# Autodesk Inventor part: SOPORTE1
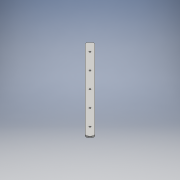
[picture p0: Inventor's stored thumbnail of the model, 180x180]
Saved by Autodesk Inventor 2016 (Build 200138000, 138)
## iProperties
Created: 2016-06
Part Number: SOPORTE1
Material: Genérico
Document SubType Name: Modeling
Designer: adm
Density: 1 g/cm^3
Appearance: Valor por defecto
Author: adm
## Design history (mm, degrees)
sketch "Boceto1"
  geometry: L1 (166.17, -187.383)-(187.383, -166.17); L2 (187.383, -166.17)-(-166.17, 187.383); L3 (-166.17, 187.383)-(-187.383, 166.17); L4 (-187.383, 166.17)-(166.17, -187.383); L5 (166.17, -187.383)-(-166.17, 187.383); L6 (187.383, -166.17)-(-187.383, 166.17); L7 (166.17, -187.383)-(196.17, -187.383); C1 r 3.5 at (-141.421, 141.421); C2 r 3.5 at (-70.711, 70.711); C3 r 3.5 at (0, 0); C4 r 3.5 at (70.711, -70.711); C5 r 3.5 at (141.421, -141.421); 6 further points
  constraints: 14 end point, 5 centre point, 5 coincident, 2 midpoint, 2 parallel, 1 equal length, 1 horizontal, 1 perpendicular
  dimensions: "d0" = 30 distance of L1.start L1.end; "d1" = 45 deg angle of L7 L1; "d2" = 500 distance of L2.end L1.end; "d3" = 50 distance from line of point (-141.421, 141.421) L3; "d4" = 50 distance from line of point (141.421, -141.421) L1; "d5" = 150 distance from line of point (-70.711, 70.711) L3; "d6" = 250 distance from line of point (0, 0) L3; "d7" = 350 distance from line of point (70.711, -70.711) L3; "d8" = 7 diameter of C1; "d9" = 7 diameter of C2; "d10" = 7 diameter of C3; "d11" = 7 diameter of C4; "d12" = 7 diameter of C5
extrude "Extrusión1" new body sketch "Boceto1" distance "d13" = 6; taper "d14" = 0 deg
fillet "Empalme1" dims "d15" = 10
sketch "Boceto2"
  geometry: L1 (75.83, -250.705)-(156.742, -154.277); L2 (57.177, -210.705)-(126.1, -128.566); L3 (34.196, -221.421)-(-203.95, -221.421); L4 (52.848, -261.421)-(-289.73, -261.421); L5 (-86.032, 83.566)-(-320.372, -195.71); L6 (-54.102, 59.39)-(-234.592, -155.71); C1 r 3.5 at (-141.421, 141.421) reference; A1 r 40 centre (-289.73, -221.421) between (-320.372, -195.71) and (-289.73, -261.421); A2 r 40 centre (-203.95, -181.421) between (-234.592, -155.71) and (-203.95, -221.421); A3 r 20.1 centre (-70.711, 70.711) between (-56.678, 56.32) and (-87.319, 82.032); A4 r 20 centre (141.421, -141.421) between (156.742, -154.277) and (126.1, -128.566); A5 r 30 centre (34.196, -191.421) between (34.196, -221.421) and (57.177, -210.705); A6 r 30 centre (52.848, -231.421) between (52.848, -261.421) and (75.83, -250.705); 3 further points
  constraints: 13 point on circle, 12 end point, 9 tangent, 6 centre point, 2 coincident, 2 point on line
  dimensions: "d26" = 40 radius of A1; "d27" = 50 deg angle of L5 L4; "d28" = 40 radius of A2; "d29" = 30 radius of A5; "d30" = 30 radius of A6
node "Sólido1"
